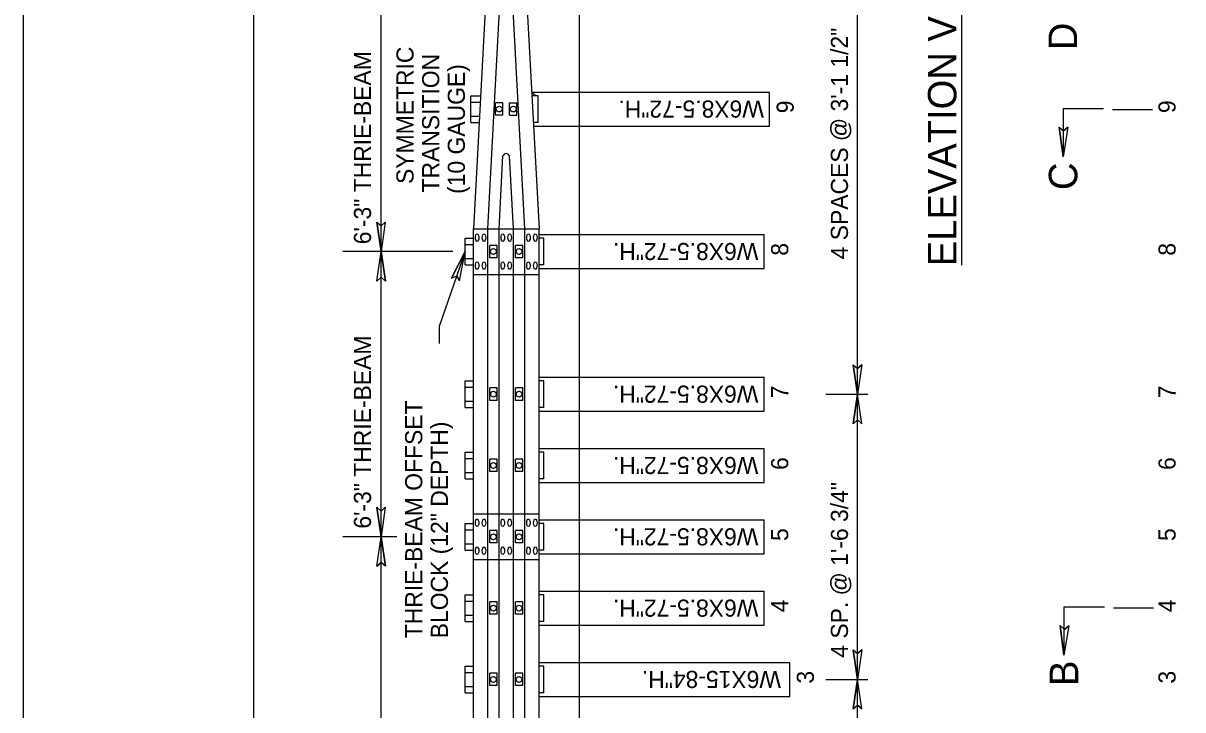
# Model space of a CAD drawing. Extents: x 12.2 to 54.5, y -7.8 to 16.1.
# Drawn here: x 46.034 to 50.1, y -3.938 to -1.531 of the extents above; entities that cross this region are included whole.
import ezdxf

# ---------------------------------------------------------------- set-up
doc = ezdxf.new("R2010")
doc.units = 0
for name, color, linetype in [('BORD-LINE', 7, 'Continuous'), ('DETL-DIMS', 7, 'Continuous'), ('DETL-LINE', 7, 'Continuous'), ('DETL-NOTE', 7, 'Continuous'), ('DETL-PATT', 7, 'Continuous'), ('DETL-TITL', 7, 'Continuous'), ('USER-BORD', 7, 'Continuous')]:
    doc.layers.add(name, color=color, linetype=linetype)

msp = doc.modelspace()

# ---------------------------------------------------------------- linework, layer by layer
at = {"layer": 'BORD-LINE'}
msp.add_lwpolyline([(46.8431, 2.8902), (54.2173, 2.8902), (54.2173, -7.4629), (46.8431, -7.4629)], close=True, dxfattribs=at)
at = {"layer": 'DETL-DIMS'}
for p, q in [((48.96, -2.832), (48.96, -0.832)), ((47.289, -5.5129), (47.289, -1.332)), ((47.6579, -1.412), (47.6129, -2.252)), ((47.6629, -2.252), (47.7079, -1.412)), ((47.7929, -2.252), (47.7479, -1.412)), ((47.7979, -1.412), (47.8429, -2.252)), ((49.6805, -1.8301), (49.6805, -1.9994)), ((49.6805, -1.8301), (49.8221, -1.8301)), ((49.8539, -1.8336), (49.9946, -1.8336)), ((50.1004, -1.832), (50.1004, -1.832)), ((50.1004, -1.832), (50.1004, -1.832)), ((49.667, -1.8958), (49.6805, -1.9994)), ((49.667, -1.8958), (49.6819, -1.9089)), ((49.6972, -1.8963), (49.6805, -1.9994)), ((49.6972, -1.8963), (49.6819, -1.9089)), ((47.7029, -2.252), (47.7166, -1.997)), ((47.7529, -2.252), (47.7393, -1.997)), ((47.2739, -2.2287), (47.289, -2.332)), ((47.2739, -2.2287), (47.289, -2.2416)), ((47.304, -2.2287), (47.289, -2.332)), ((47.304, -2.2287), (47.289, -2.2416)), ((47.5412, -2.332), (47.1551, -2.332)), ((47.274, -2.4353), (47.289, -2.332)), ((47.3041, -2.4353), (47.289, -2.332)), ((47.5837, -2.332), (47.494, -2.5917)), ((47.5358, -2.4248), (47.5837, -2.332)), ((47.5642, -2.4346), (47.5837, -2.332)), ((50.1004, -2.332), (50.1004, -2.332)), ((50.1004, -2.332), (50.1004, -2.332)), ((47.274, -2.4353), (47.289, -2.4224)), ((47.3041, -2.4353), (47.289, -2.4224)), ((47.5358, -2.4248), (47.5542, -2.4174)), ((47.5642, -2.4346), (47.5542, -2.4174)), ((47.494, -2.6548), (47.494, -2.5917)), ((48.945, -2.7286), (48.96, -2.832)), ((48.945, -2.7286), (48.96, -2.7416)), ((48.9751, -2.7286), (48.96, -2.832)), ((48.9751, -2.7286), (48.96, -2.7416)), ((48.8482, -2.832), (48.9965, -2.832)), ((48.945, -2.9354), (48.96, -2.832)), ((48.96, -3.832), (48.96, -2.832)), ((48.96, -4.832), (48.96, -2.832)), ((48.9751, -2.9354), (48.96, -2.832)), ((50.1004, -2.832), (50.1004, -2.832)), ((50.1004, -2.832), (50.1004, -2.832)), ((48.945, -2.9354), (48.96, -2.9224)), ((48.9751, -2.9354), (48.96, -2.9224)), ((50.1004, -3.082), (50.1004, -3.082)), ((50.1004, -3.082), (50.1004, -3.082)), ((50.1004, -3.082), (50.1004, -3.082)), ((47.2739, -3.2287), (47.289, -3.332)), ((47.2739, -3.2287), (47.289, -3.2416)), ((47.304, -3.2287), (47.289, -3.332)), ((47.304, -3.2287), (47.289, -3.2416)), ((47.3445, -3.332), (47.1551, -3.332)), ((47.274, -3.4353), (47.289, -3.332)), ((47.3041, -3.4353), (47.289, -3.332)), ((50.1004, -3.332), (50.1004, -3.332)), ((50.1004, -3.332), (50.1004, -3.332)), ((48.96, -4.832), (48.96, -3.3444)), ((47.274, -3.4353), (47.289, -3.4224)), ((47.3041, -3.4353), (47.289, -3.4224)), ((49.6837, -3.5777), (49.6837, -3.747)), ((49.6837, -3.5777), (49.8253, -3.5777)), ((49.8571, -3.5812), (49.9979, -3.5812)), ((50.1004, -3.582), (50.1004, -3.582)), ((50.1004, -3.582), (50.1004, -3.582)), ((49.6702, -3.6434), (49.6837, -3.747)), ((49.6702, -3.6434), (49.6851, -3.6565)), ((49.7004, -3.6439), (49.6837, -3.747)), ((49.7004, -3.6439), (49.6851, -3.6565)), ((48.945, -3.7286), (48.96, -3.832)), ((48.945, -3.7286), (48.96, -3.7416)), ((48.9751, -3.7286), (48.96, -3.832)), ((48.9751, -3.7286), (48.96, -3.7416)), ((48.8482, -3.832), (48.9965, -3.832)), ((48.945, -3.9354), (48.96, -3.832)), ((48.96, -4.832), (48.96, -3.832)), ((48.9751, -3.9354), (48.96, -3.832)), ((50.1004, -3.832), (50.1004, -3.832)), ((50.1004, -3.832), (50.1004, -3.832)), ((48.945, -3.9354), (48.96, -3.9224)), ((48.9751, -3.9354), (48.96, -3.9224))]:
    msp.add_line(p, q, dxfattribs=at)
for points in [[(49.6972, -1.8963), (49.6805, -1.9994), (49.667, -1.8958), (49.6819, -1.9089)], [(47.304, -2.2287), (47.289, -2.332), (47.2739, -2.2287), (47.289, -2.2416)], [(47.274, -2.4353), (47.289, -2.332), (47.3041, -2.4353), (47.289, -2.4224)], [(47.5642, -2.4346), (47.5837, -2.332), (47.5358, -2.4248), (47.5542, -2.4174)], [(48.9751, -2.7286), (48.96, -2.832), (48.945, -2.7286), (48.96, -2.7416)], [(48.9751, -2.9354), (48.96, -2.832), (48.945, -2.9354), (48.96, -2.9224)], [(47.304, -3.2287), (47.289, -3.332), (47.2739, -3.2287), (47.289, -3.2416)], [(47.274, -3.4353), (47.289, -3.332), (47.3041, -3.4353), (47.289, -3.4224)], [(49.7004, -3.6439), (49.6837, -3.747), (49.6702, -3.6434), (49.6851, -3.6565)], [(48.9751, -3.7286), (48.96, -3.832), (48.945, -3.7286), (48.96, -3.7416)], [(48.9751, -3.9354), (48.96, -3.832), (48.945, -3.9354), (48.96, -3.9224)]]:
    msp.add_lwpolyline(points, close=True, dxfattribs=at)
at = {"layer": 'DETL-LINE'}
for p, q in [((47.9832, 2.7851), (47.9832, -5.332)), ((47.6041, -1.7859), (47.6379, -1.7859)), ((47.6041, -1.8792), (47.6041, -1.7859)), ((47.8173, -1.7729), (48.0026, -1.7729)), ((47.8403, -1.7859), (47.818, -1.7859)), ((47.8403, -1.8792), (47.8403, -1.7859)), ((48.0026, -1.7729), (48.2591, -1.7729)), ((48.0026, -1.7729), (48.6516, -1.7729)), ((48.6516, -1.8922), (48.6516, -1.7729)), ((47.6041, -1.808), (47.6367, -1.808)), ((47.7161, -1.8109), (47.6905, -1.8109)), ((47.6905, -1.8542), (47.6905, -1.8109)), ((47.7161, -1.8542), (47.7161, -1.8109)), ((47.7397, -1.8109), (47.7653, -1.8109)), ((47.7397, -1.8542), (47.7397, -1.8109)), ((47.7653, -1.8542), (47.7653, -1.8109)), ((47.6041, -1.8571), (47.6341, -1.8571)), ((47.7161, -1.8542), (47.6905, -1.8542)), ((47.7397, -1.8542), (47.7653, -1.8542)), ((47.6041, -1.8792), (47.6333, -1.8792)), ((47.8403, -1.8792), (47.8237, -1.8792)), ((47.8237, -1.8922), (48.0026, -1.8922)), ((48.0026, -1.8922), (48.2591, -1.8922)), ((48.0026, -1.8922), (48.6516, -1.8922)), ((47.6129, -2.252), (47.8429, -2.252)), ((47.6129, -5.332), (47.6129, -2.252)), ((47.6629, -5.332), (47.6629, -2.252)), ((47.7029, -5.332), (47.7029, -2.252)), ((47.7529, -5.332), (47.7529, -2.252)), ((47.7929, -5.332), (47.7929, -2.252)), ((47.8429, -5.332), (47.8429, -2.252)), ((47.8429, -2.2723), (47.9832, -2.2723)), ((47.9832, -2.2723), (48.6323, -2.2723)), ((48.6323, -2.3916), (48.6323, -2.2723)), ((47.5837, -2.2853), (47.6129, -2.2853)), ((47.5837, -2.3786), (47.5837, -2.2853)), ((47.5837, -2.3074), (47.6129, -2.3074)), ((47.6957, -2.3103), (47.6701, -2.3103)), ((47.6701, -2.3536), (47.6701, -2.3103)), ((47.6957, -2.3536), (47.6957, -2.3103)), ((47.7857, -2.3103), (47.7601, -2.3103)), ((47.7601, -2.3536), (47.7601, -2.3103)), ((47.7857, -2.3536), (47.7857, -2.3103)), ((47.8596, -2.2853), (47.8429, -2.2853)), ((47.8596, -2.3786), (47.8596, -2.2853)), ((47.5837, -2.3565), (47.6129, -2.3565)), ((47.6957, -2.3536), (47.6701, -2.3536)), ((47.7857, -2.3536), (47.7601, -2.3536)), ((47.5837, -2.3786), (47.6129, -2.3786)), ((47.8596, -2.3786), (47.8429, -2.3786)), ((47.8429, -2.3916), (47.9832, -2.3916)), ((47.9832, -2.3916), (48.6323, -2.3916)), ((47.6129, -2.412), (47.8429, -2.412)), ((47.5837, -2.7853), (47.6129, -2.7853)), ((47.5837, -2.8786), (47.5837, -2.7853)), ((47.8429, -2.7723), (47.9832, -2.7723)), ((47.8596, -2.7853), (47.8429, -2.7853)), ((47.8596, -2.8786), (47.8596, -2.7853)), ((47.9832, -2.7723), (48.6323, -2.7723)), ((48.6323, -2.8916), (48.6323, -2.7723)), ((47.5837, -2.8074), (47.6129, -2.8074)), ((47.6957, -2.8103), (47.6701, -2.8103)), ((47.6701, -2.8536), (47.6701, -2.8103)), ((47.6957, -2.8536), (47.6957, -2.8103)), ((47.7857, -2.8103), (47.7601, -2.8103)), ((47.7601, -2.8536), (47.7601, -2.8103)), ((47.7857, -2.8536), (47.7857, -2.8103)), ((47.5837, -2.8565), (47.6129, -2.8565)), ((47.5837, -2.8786), (47.6129, -2.8786)), ((47.6957, -2.8536), (47.6701, -2.8536)), ((47.7857, -2.8536), (47.7601, -2.8536)), ((47.8596, -2.8786), (47.8429, -2.8786)), ((47.8429, -2.8916), (47.9832, -2.8916)), ((47.9832, -2.8916), (48.6323, -2.8916)), ((47.5837, -3.0353), (47.6129, -3.0353)), ((47.5837, -3.1286), (47.5837, -3.0353)), ((47.8429, -3.0223), (47.9832, -3.0223)), ((47.8596, -3.0353), (47.8429, -3.0353)), ((47.8596, -3.1286), (47.8596, -3.0353)), ((47.9832, -3.0223), (48.6323, -3.0223)), ((48.6323, -3.1416), (48.6323, -3.0223)), ((47.5837, -3.0574), (47.6129, -3.0574)), ((47.6957, -3.0603), (47.6701, -3.0603)), ((47.6701, -3.1036), (47.6701, -3.0603)), ((47.6957, -3.1036), (47.6957, -3.0603)), ((47.7857, -3.0603), (47.7601, -3.0603)), ((47.7601, -3.1036), (47.7601, -3.0603)), ((47.7857, -3.1036), (47.7857, -3.0603)), ((47.5837, -3.1065), (47.6129, -3.1065)), ((47.5837, -3.1286), (47.6129, -3.1286)), ((47.6957, -3.1036), (47.6701, -3.1036)), ((47.7857, -3.1036), (47.7601, -3.1036)), ((47.8596, -3.1286), (47.8429, -3.1286)), ((47.8429, -3.1416), (47.9832, -3.1416)), ((47.9832, -3.1416), (48.6323, -3.1416)), ((47.6129, -3.252), (47.8429, -3.252)), ((47.5837, -3.2853), (47.6129, -3.2853)), ((47.5837, -3.3786), (47.5837, -3.2853)), ((47.8429, -3.2723), (47.9832, -3.2723)), ((47.8596, -3.2853), (47.8429, -3.2853)), ((47.8596, -3.3786), (47.8596, -3.2853)), ((47.9832, -3.2723), (48.6323, -3.2723)), ((48.6323, -3.3916), (48.6323, -3.2723)), ((47.5837, -3.3074), (47.6129, -3.3074)), ((47.6957, -3.3103), (47.6701, -3.3103)), ((47.6701, -3.3536), (47.6701, -3.3103)), ((47.6957, -3.3536), (47.6957, -3.3103)), ((47.7857, -3.3103), (47.7601, -3.3103)), ((47.7601, -3.3536), (47.7601, -3.3103)), ((47.7857, -3.3536), (47.7857, -3.3103)), ((47.5837, -3.3565), (47.6129, -3.3565)), ((47.6957, -3.3536), (47.6701, -3.3536)), ((47.7857, -3.3536), (47.7601, -3.3536)), ((47.5837, -3.3786), (47.6129, -3.3786)), ((47.6129, -3.412), (47.8429, -3.412)), ((47.8596, -3.3786), (47.8429, -3.3786)), ((47.8429, -3.3916), (47.9832, -3.3916)), ((47.9832, -3.3916), (48.6323, -3.3916)), ((47.5837, -3.5353), (47.6129, -3.5353)), ((47.5837, -3.6286), (47.5837, -3.5353)), ((47.8429, -3.5223), (47.9832, -3.5223)), ((47.8596, -3.5353), (47.8429, -3.5353)), ((47.8596, -3.6286), (47.8596, -3.5353)), ((47.9832, -3.5223), (48.6323, -3.5223)), ((48.6323, -3.6416), (48.6323, -3.5223)), ((47.5837, -3.5574), (47.6129, -3.5574)), ((47.6957, -3.5603), (47.6701, -3.5603)), ((47.6701, -3.6036), (47.6701, -3.5603)), ((47.6957, -3.6036), (47.6957, -3.5603)), ((47.7857, -3.5603), (47.7601, -3.5603)), ((47.7601, -3.6036), (47.7601, -3.5603)), ((47.7857, -3.6036), (47.7857, -3.5603)), ((47.5837, -3.6065), (47.6129, -3.6065)), ((47.6957, -3.6036), (47.6701, -3.6036)), ((47.7857, -3.6036), (47.7601, -3.6036)), ((47.5837, -3.6286), (47.6129, -3.6286)), ((47.8596, -3.6286), (47.8429, -3.6286)), ((47.8429, -3.6416), (47.9832, -3.6416)), ((47.9832, -3.6416), (48.6323, -3.6416)), ((47.8429, -3.7723), (47.9832, -3.7723)), ((47.9832, -3.7723), (48.7223, -3.7723)), ((48.7223, -3.8916), (48.7223, -3.7723)), ((47.5837, -3.7853), (47.6129, -3.7853)), ((47.5837, -3.8786), (47.5837, -3.7853)), ((47.5837, -3.8074), (47.6129, -3.8074)), ((47.6957, -3.8103), (47.6701, -3.8103)), ((47.6701, -3.8536), (47.6701, -3.8103)), ((47.6957, -3.8536), (47.6957, -3.8103)), ((47.7857, -3.8103), (47.7601, -3.8103)), ((47.7601, -3.8536), (47.7601, -3.8103)), ((47.7857, -3.8536), (47.7857, -3.8103)), ((47.8596, -3.7853), (47.8429, -3.7853)), ((47.8596, -3.8786), (47.8596, -3.7853)), ((47.5837, -3.8565), (47.6129, -3.8565)), ((47.6957, -3.8536), (47.6701, -3.8536)), ((47.7857, -3.8536), (47.7601, -3.8536)), ((47.5837, -3.8786), (47.6129, -3.8786)), ((47.8596, -3.8786), (47.8429, -3.8786)), ((47.8429, -3.8916), (47.9832, -3.8916)), ((47.9832, -3.8916), (48.7223, -3.8916))]:
    msp.add_line(p, q, dxfattribs=at)
for centre in [(47.7033, -1.8325), (47.7525, -1.8325), (47.6829, -2.332), (47.7729, -2.332), (47.6829, -2.832), (47.7729, -2.832), (47.6829, -3.082), (47.7729, -3.082), (47.6829, -3.332), (47.7729, -3.332), (47.6829, -3.582), (47.7729, -3.582), (47.6829, -3.832), (47.7729, -3.832)]:
    msp.add_circle(centre, 0.0102, dxfattribs=at)
msp.add_arc((47.7279, -2.0008), 0.012, 18.6926, 161.3074, dxfattribs=at)
for centre in [(47.6259, -2.283), (47.6499, -2.283), (47.7159, -2.283), (47.7399, -2.283), (47.8059, -2.283), (47.8299, -2.283), (47.6259, -2.381), (47.6499, -2.381), (47.7159, -2.381), (47.7399, -2.381), (47.8059, -2.381), (47.8299, -2.381), (47.6259, -3.283), (47.6499, -3.283), (47.7159, -3.283), (47.7399, -3.283), (47.8059, -3.283), (47.8299, -3.283), (47.6259, -3.381), (47.6499, -3.381), (47.7159, -3.381), (47.7399, -3.381), (47.8059, -3.381), (47.8299, -3.381)]:
    msp.add_ellipse(centre, major_axis=(0, 0.0133), ratio=0.45311, dxfattribs=at)
at = {"layer": 'DETL-PATT'}
msp.add_arc((47.7289, -1.9135), 0.1637, 51.21, 57.2611, dxfattribs=at)
at = {"layer": 'DETL-TITL'}
msp.add_line((49.3252, -2.38), (49.3252, -1.0753), dxfattribs=at)
at = {"layer": 'USER-BORD'}
msp.add_lwpolyline([(54.5342, 3.2202), (46.0342, 3.2202), (46.0342, -7.7798), (54.5342, -7.7798)], close=True, dxfattribs=at)

# ---------------------------------------------------------------- texts
at = {"layer": 'DETL-NOTE'}
for s, rotation, p in [('4 SPACES @ 3\'-1 1/2"', 90, (48.9263, -2.3594)), ('SYMMETRIC', 90, (47.403, -2.095)), ('6\'-3" THRIE-BEAM', 90, (47.2539, -2.3065)), ('TRANSITION', 90, (47.493, -2.1249)), ('(10 GAUGE)', 90, (47.583, -2.13)), ('W6X8.5-72"H. ', 180, (48.6315, -1.8025)), ('9', 90, (48.7361, -1.8472)), ('9', 90, (50.075, -1.8466)), ('W6X8.5-72"H. ', 180, (48.6121, -2.302)), ('8', 90, (48.7168, -2.3466)), ('8', 90, (50.075, -2.3466)), ('6\'-3" THRIE-BEAM', 90, (47.2539, -3.3035)), ('W6X8.5-72"H. ', 180, (48.6121, -2.802)), ('7', 90, (48.7168, -2.8466)), ('7', 90, (50.075, -2.8466)), ('THRIE-BEAM OFFSET ', 90, (47.4336, -3.6877)), ('BLOCK (12" DEPTH)', 90, (47.5236, -3.6877)), ('W6X8.5-72"H. ', 180, (48.6121, -3.052)), ('6', 90, (48.7168, -3.0977)), ('6', 90, (50.075, -3.0977)), ('4 SP. @ 1\'-6 3/4"', 90, (48.9263, -3.7559)), ('W6X8.5-72"H. ', 180, (48.6121, -3.302)), ('5', 90, (48.7168, -3.3466)), ('5', 90, (50.075, -3.3466)), ('W6X8.5-72"H. ', 180, (48.6121, -3.552)), ('4', 90, (48.7168, -3.5966)), ('4', 90, (50.075, -3.5966)), ('W6X15-84"H. ', 180, (48.6914, -3.802)), ('3', 90, (48.8068, -3.8466)), ('3', 90, (50.075, -3.8466))]:
    msp.add_text(s, height=0.06, rotation=rotation, dxfattribs=at).set_placement(p)
at = {"layer": 'DETL-TITL'}
for s, p in [('ELEVATION VIEW', (49.3066, -2.3836)), ('D', (49.7296, -1.6261)), ('C', (49.7305, -2.1165)), ('B', (49.7337, -3.855))]:
    msp.add_text(s, height=0.1, rotation=90, dxfattribs=at).set_placement(p)

doc.saveas('drawing.dxf')
